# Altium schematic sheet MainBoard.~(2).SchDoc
size A4
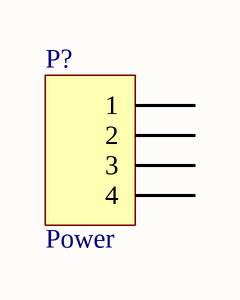
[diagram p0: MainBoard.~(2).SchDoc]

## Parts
P?  Power  [HDR1X4]

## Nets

Not connected (* = marked no-connect by the designer): P? 1 2 3 4

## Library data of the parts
P? = Header 4: Header, 4-Pin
